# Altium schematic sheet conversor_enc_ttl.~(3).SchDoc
size A4
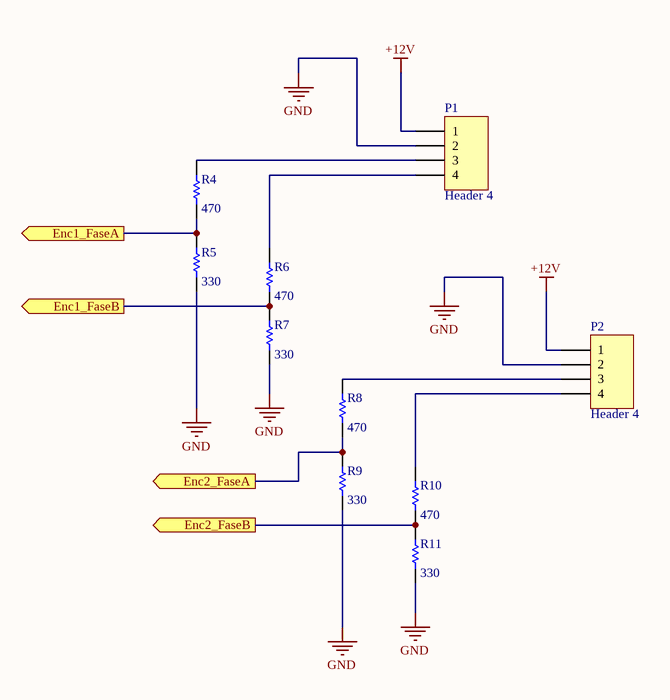
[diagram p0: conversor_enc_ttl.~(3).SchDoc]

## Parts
P1  Header 4  [HDR1X4]
P2  Header 4  [HDR1X4]
R4  value 470  [1005[0402]]  (hidden comment: metal film 2%)
R5  value 330  [1005[0402]]  (hidden comment: metal film 2%)
R6  value 470  [1005[0402]]  (hidden comment: metal film 2%)
R7  value 330  [1005[0402]]  (hidden comment: metal film 2%)
R8  value 470  [1005[0402]]  (hidden comment: metal film 2%)
R9  value 330  [1005[0402]]  (hidden comment: metal film 2%)
R10  value 470  [1005[0402]]  (hidden comment: metal film 2%)
R11  value 330  [1005[0402]]  (hidden comment: metal film 2%)

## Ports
Enc1_FaseA (out), Enc1_FaseB (out), Enc2_FaseA (out), Enc2_FaseB (out)

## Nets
+12V: P1.1 P2.1
GND: P1.2 P2.2 R5.1 R7.1 R9.1 R11.1
Enc1_FaseA: R4.1 R5.2 ; port Enc1_FaseA
Enc1_FaseB: R6.1 R7.2 ; port Enc1_FaseB
Enc2_FaseA: R8.1 R9.2 ; port Enc2_FaseA
Enc2_FaseB: R10.1 R11.2 ; port Enc2_FaseB
NetP1_3: P1.3 R4.2
NetP1_4: P1.4 R6.2
NetP2_3: P2.3 R8.2
NetP2_4: P2.4 R10.2

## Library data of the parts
P1 P2 = Header 4: Header, 4-Pin
R4-R11 = Res Semi: Semiconductor Resistor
